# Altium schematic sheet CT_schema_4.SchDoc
size 229 x 185 mm
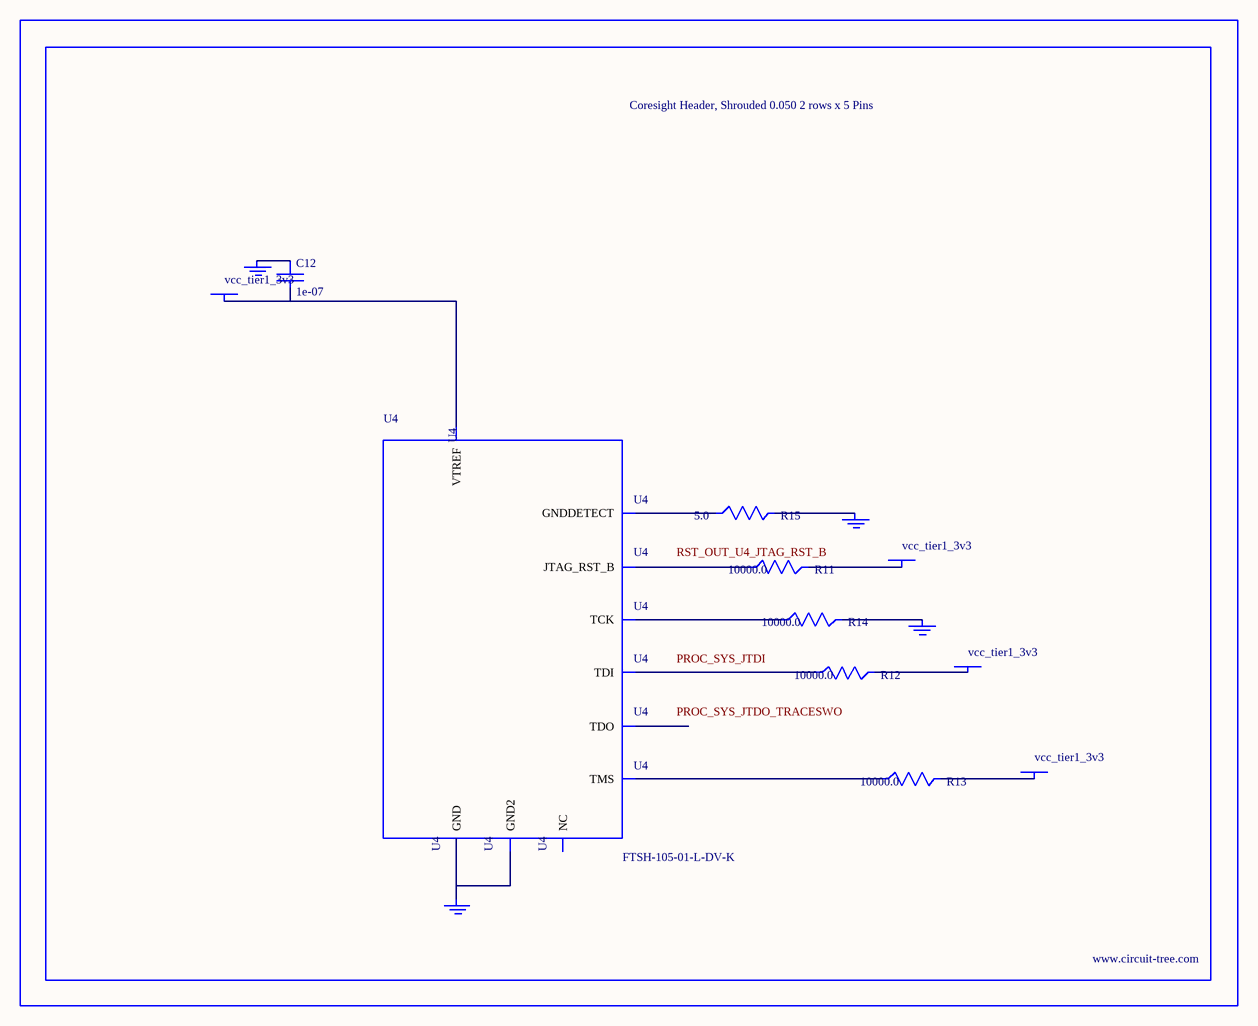
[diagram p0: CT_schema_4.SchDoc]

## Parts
BORDER3  (no value)
C12  1e-07  [C0402]
GND_INSTANCE_3_0  (no value)
GND_INSTANCE_3_1  (no value)
GND_INSTANCE_3_2  (no value)
GND_INSTANCE_3_3  (no value)
POWER_INSTANCE_3_0  vcc_tier1_3v3
POWER_INSTANCE_3_1  vcc_tier1_3v3
POWER_INSTANCE_3_2  vcc_tier1_3v3
POWER_INSTANCE_3_3  vcc_tier1_3v3
R11  10000.0  [R0603]
R12  10000.0  [R0603]
R13  10000.0  [R0603]
R14  10000.0  [R0603]
R15  5.0  [R0603]
U4  FTSH-105-01-L-DV-K  [SAMTEC_FTSH-105-01-L-DV-K]

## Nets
NetC12_1: C12.1 GND_INSTANCE_3_0.0(GND)
NetC12_2: C12.2 POWER_INSTANCE_3_0.0(PWR) U4.1(VTREF)
NetGND_INSTANCE_3_1_0: GND_INSTANCE_3_1.0(GND) R14.2
NetGND_INSTANCE_3_2_0: GND_INSTANCE_3_2.0(GND) R15.2
NetGND_INSTANCE_3_3_0: GND_INSTANCE_3_3.0(GND) U4.3(GND) U4.5(GND2)
NetPOWER_INSTANCE_3_1_0: POWER_INSTANCE_3_1.0(PWR) R13.2
NetPOWER_INSTANCE_3_2_0: POWER_INSTANCE_3_2.0(PWR) R12.2
NetPOWER_INSTANCE_3_3_0: POWER_INSTANCE_3_3.0(PWR) R11.2
NetR11_1: R11.1 U4.10(JTAG_RST_B)
NetR12_1: R12.1 U4.8(TDI)
NetR13_1: R13.1 U4.2(TMS)
NetR14_1: R14.1 U4.4(TCK)
NetR15_1: R15.1 U4.9(GNDDETECT)

Not connected (* = marked no-connect by the designer): U4 6(TDO) 7(NC)

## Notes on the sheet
- Labels drawn without touching a wire or pin: PROC_SYS_JTDI, PROC_SYS_JTDO_TRACESWO, RST_OUT_U4_JTAG_RST_B

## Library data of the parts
BORDER3 = BORDER_PAGE3
C12 = C0402C104K3RACTU
GND_INSTANCE_3_0-GND_INSTANCE_3_3 = GND
POWER_INSTANCE_3_0-POWER_INSTANCE_3_3 = PWR
R11-R14 = RC0603JR-0710KL
R15 = ERJ-3GEYJ5R1V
